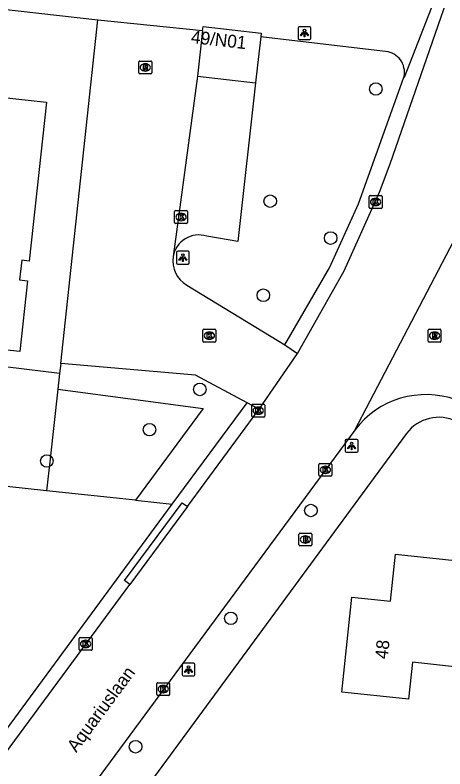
# Model space of a CAD drawing. Extents: x 162398 to 163643, y 386453 to 387397.
# Drawn here: x 162867.5 to 162900.9, y 386898.2 to 386956.9 of the extents above; entities that cross this region are included whole.
import ezdxf

# ---------------------------------------------------------------- set-up
doc = ezdxf.new("R2010")
doc.units = 0
for name, color, linetype in [('IMGEO_Boom', 7, 'Continuous'), ('IMGEO_Brandkraan', 7, 'Continuous'), ('IMGEO_Groenvoorziening', 7, 'Continuous'), ('IMGEO_Kolk', 7, 'Continuous'), ('IMGEO_Lichtpunt', 7, 'Continuous'), ('IMGEO_Openbare_ruimte_label', 7, 'Continuous'), ('IMGEO_Pand', 7, 'Continuous'), ('IMGEO_Pand_nummerreeks', 7, 'Continuous'), ('IMGEO_Parkeervlak_open', 7, 'Continuous'), ('IMGEO_Rijbaan_lokaal_open', 7, 'Continuous'), ('IMGEO_Rioolput', 7, 'Continuous'), ('IMGEO_Voetpad_open', 7, 'Continuous')]:
    doc.layers.add(name, color=color, linetype=linetype)

msp = doc.modelspace()

# ---------------------------------------------------------------- linework, layer by layer
at = {"layer": 'IMGEO_Boom'}
for centre in [(162895.569, 386951.153), (162887.351, 386942.42), (162892.053, 386939.544), (162886.814, 386935.093), (162881.877, 386927.759), (162877.957, 386924.62), (162869.974, 386922.184), (162890.515, 386918.327), (162884.29, 386909.926), (162876.874, 386899.924)]:
    msp.add_circle(centre, 0.489, dxfattribs=at)
at = {"layer": 'IMGEO_Brandkraan'}
for p, q in [((162889.59, 386915.641), (162889.59, 386916.493)), ((162889.665, 386916.567), (162890.517, 386916.567)), ((162890.078, 386916.347), (162890.103, 386916.347)), ((162890.591, 386916.493), (162890.591, 386915.641)), ((162890.101, 386915.787), (162890.076, 386915.787)), ((162890.517, 386915.567), (162889.665, 386915.567))]:
    msp.add_line(p, q, dxfattribs=at)
for points in [[(162889.59, 386915.641), (162889.59, 386916.493)], [(162889.665, 386916.567), (162890.517, 386916.567)], [(162889.938, 386916.267), (162889.938, 386915.867), (162890.151, 386915.867)], [(162890.169, 386916.267), (162889.938, 386916.267)], [(162890.591, 386916.493), (162890.591, 386915.641)], [(162890.117, 386916.186), (162890.063, 386916.186), (162890.063, 386916.11)], [(162890.063, 386916.11), (162890.116, 386916.11)], [(162890.125, 386916.034), (162890.063, 386916.034), (162890.063, 386915.953)], [(162890.063, 386915.953), (162890.125, 386915.953)], [(162890.517, 386915.567), (162889.665, 386915.567)]]:
    msp.add_lwpolyline(points, dxfattribs=at)
for centre, radius, start, end in [((162889.667, 386916.491), 0.0765, 91.55205, 178.44795), ((162889.667, 386916.491), 0.0765, 91.55205, 178.44795), ((162890.173, 386916.122), 0.145, 59.4692, 91.53667), ((162890.515, 386916.491), 0.0765, 1.55205, 88.44795), ((162890.515, 386916.491), 0.0765, 1.55205, 88.44795), ((162890.118, 386916.148), 0.0379, 267.82845, 90.93552), ((162890.126, 386915.993), 0.0404, 269.87594, 90.50774), ((162890.157, 386916.118), 0.251, 268.66757, 293.53466), ((162890.198, 386916.169), 0.0922, 285.51372, 58.15012), ((162890.203, 386915.977), 0.105, 301.31148, 78.98903), ((162889.667, 386915.643), 0.0765, 181.55205, 268.44795), ((162889.667, 386915.643), 0.0765, 181.55205, 268.44795), ((162890.515, 386915.643), 0.0765, 271.55205, 358.44795), ((162890.515, 386915.643), 0.0765, 271.55205, 358.44795)]:
    msp.add_arc(centre, radius, start, end, dxfattribs=at)
for centre, major_axis, ratio, start_param, end_param in [((162890.077, 386916.067), (-0.387, 0.002), 0.722429, 4.712389, 7.853982), ((162890.102, 386916.067), (-0.39, 0.002), 0.717154, 1.570796, 4.712389)]:
    msp.add_ellipse(centre, major_axis=major_axis, ratio=ratio, start_param=start_param, end_param=end_param, dxfattribs=at)
at = {"layer": 'IMGEO_Groenvoorziening'}
for points in [[(162870.971, 386929.009), (162859.945, 386930.347), (162828.236, 386933.706), (162820.477, 386934.559), (162809.62, 386935.738), (162809.662, 386936.561)], [(162871.058, 386929.777), (162870.971, 386929.009)], [(162870.971, 386929.009), (162870.833, 386927.783)], [(162870.833, 386927.783), (162870.223, 386922.353), (162869.944, 386919.868)], [(162870.833, 386927.783), (162882.122, 386926.262), (162876.858, 386919.124)], [(162869.944, 386919.868), (162863.993, 386920.509)], [(162876.858, 386919.124), (162869.944, 386919.868)], [(162876.858, 386919.124), (162879.736, 386918.814)]]:
    msp.add_lwpolyline(points, dxfattribs=at)
at = {"layer": 'IMGEO_Kolk'}
for p, q in [((162895.047, 386941.932), (162895.047, 386942.784)), ((162895.122, 386942.858), (162895.974, 386942.858)), ((162896.048, 386942.784), (162896.048, 386941.932)), ((162895.535, 386942.638), (162895.56, 386942.638)), ((162879.915, 386940.755), (162879.915, 386941.607)), ((162879.99, 386941.681), (162880.842, 386941.681)), ((162880.916, 386941.607), (162880.916, 386940.755)), ((162895.974, 386941.858), (162895.122, 386941.858)), ((162895.558, 386942.078), (162895.533, 386942.078)), ((162880.403, 386941.461), (162880.428, 386941.461)), ((162880.842, 386940.681), (162879.99, 386940.681)), ((162880.426, 386940.901), (162880.401, 386940.901)), ((162882.116, 386931.514), (162882.116, 386932.366)), ((162882.191, 386932.44), (162883.043, 386932.44)), ((162882.604, 386932.22), (162882.629, 386932.22)), ((162883.117, 386932.366), (162883.117, 386931.514)), ((162882.627, 386931.66), (162882.602, 386931.66)), ((162883.043, 386931.44), (162882.191, 386931.44)), ((162885.92, 386925.681), (162885.92, 386926.533)), ((162885.995, 386926.607), (162886.847, 386926.607)), ((162886.408, 386926.387), (162886.433, 386926.387)), ((162886.921, 386926.533), (162886.921, 386925.681)), ((162886.431, 386925.827), (162886.406, 386925.827)), ((162886.847, 386925.607), (162885.995, 386925.607)), ((162891.141, 386921.068), (162891.141, 386921.92)), ((162891.216, 386921.994), (162892.068, 386921.994)), ((162891.629, 386921.774), (162891.654, 386921.774)), ((162892.142, 386921.92), (162892.142, 386921.068)), ((162892.068, 386920.994), (162891.216, 386920.994)), ((162891.652, 386921.214), (162891.627, 386921.214)), ((162872.486, 386907.51), (162872.486, 386908.362)), ((162872.561, 386908.436), (162873.413, 386908.436)), ((162872.974, 386908.216), (162872.999, 386908.216)), ((162873.487, 386908.362), (162873.487, 386907.51)), ((162872.997, 386907.656), (162872.972, 386907.656)), ((162873.413, 386907.436), (162872.561, 386907.436)), ((162878.526, 386903.988), (162878.526, 386904.84)), ((162878.601, 386904.914), (162879.453, 386904.914)), ((162879.014, 386904.694), (162879.039, 386904.694)), ((162879.527, 386904.84), (162879.527, 386903.988)), ((162879.037, 386904.134), (162879.012, 386904.134)), ((162879.453, 386903.914), (162878.601, 386903.914))]:
    msp.add_line(p, q, dxfattribs=at)
for points in [[(162895.047, 386941.932), (162895.047, 386942.784)], [(162895.122, 386942.858), (162895.974, 386942.858)], [(162896.048, 386942.784), (162896.048, 386941.932)], [(162895.368, 386942.558), (162895.491, 386942.558), (162895.491, 386942.407), (162895.621, 386942.558), (162895.785, 386942.558), (162895.639, 386942.407), (162895.792, 386942.158), (162895.64, 386942.158), (162895.555, 386942.322), (162895.491, 386942.255), (162895.491, 386942.158), (162895.368, 386942.158), (162895.368, 386942.558)], [(162879.915, 386940.755), (162879.915, 386941.607)], [(162879.99, 386941.681), (162880.842, 386941.681)], [(162880.916, 386941.607), (162880.916, 386940.755)], [(162895.974, 386941.858), (162895.122, 386941.858)], [(162880.236, 386941.381), (162880.359, 386941.381), (162880.359, 386941.23), (162880.489, 386941.381), (162880.653, 386941.381), (162880.507, 386941.23), (162880.66, 386940.981), (162880.508, 386940.981), (162880.423, 386941.145), (162880.359, 386941.078), (162880.359, 386940.981), (162880.236, 386940.981), (162880.236, 386941.381)], [(162880.842, 386940.681), (162879.99, 386940.681)], [(162882.116, 386931.514), (162882.116, 386932.366)], [(162882.191, 386932.44), (162883.043, 386932.44)], [(162882.437, 386932.14), (162882.56, 386932.14), (162882.56, 386931.989), (162882.69, 386932.14), (162882.854, 386932.14), (162882.708, 386931.989), (162882.861, 386931.74), (162882.709, 386931.74), (162882.624, 386931.904), (162882.56, 386931.837), (162882.56, 386931.74), (162882.437, 386931.74), (162882.437, 386932.14)], [(162883.117, 386932.366), (162883.117, 386931.514)], [(162883.043, 386931.44), (162882.191, 386931.44)], [(162885.92, 386925.681), (162885.92, 386926.533)], [(162885.995, 386926.607), (162886.847, 386926.607)], [(162886.241, 386926.307), (162886.364, 386926.307), (162886.364, 386926.156), (162886.494, 386926.307), (162886.658, 386926.307), (162886.512, 386926.156), (162886.665, 386925.907), (162886.513, 386925.907), (162886.428, 386926.071), (162886.364, 386926.004), (162886.364, 386925.907), (162886.241, 386925.907), (162886.241, 386926.307)], [(162886.921, 386926.533), (162886.921, 386925.681)], [(162886.847, 386925.607), (162885.995, 386925.607)], [(162891.141, 386921.068), (162891.141, 386921.92)], [(162891.216, 386921.994), (162892.068, 386921.994)], [(162891.462, 386921.694), (162891.585, 386921.694), (162891.585, 386921.543), (162891.715, 386921.694), (162891.879, 386921.694), (162891.733, 386921.543), (162891.886, 386921.294), (162891.734, 386921.294), (162891.649, 386921.458), (162891.585, 386921.391), (162891.585, 386921.294), (162891.462, 386921.294), (162891.462, 386921.694)], [(162892.142, 386921.92), (162892.142, 386921.068)], [(162892.068, 386920.994), (162891.216, 386920.994)], [(162872.486, 386907.51), (162872.486, 386908.362)], [(162872.561, 386908.436), (162873.413, 386908.436)], [(162872.807, 386908.136), (162872.93, 386908.136), (162872.93, 386907.985), (162873.06, 386908.136), (162873.224, 386908.136), (162873.078, 386907.985), (162873.231, 386907.736), (162873.079, 386907.736), (162872.994, 386907.9), (162872.93, 386907.833), (162872.93, 386907.736), (162872.807, 386907.736), (162872.807, 386908.136)], [(162873.487, 386908.362), (162873.487, 386907.51)], [(162873.413, 386907.436), (162872.561, 386907.436)], [(162878.526, 386903.988), (162878.526, 386904.84)], [(162878.601, 386904.914), (162879.453, 386904.914)], [(162878.847, 386904.614), (162878.97, 386904.614), (162878.97, 386904.463), (162879.1, 386904.614), (162879.264, 386904.614), (162879.118, 386904.463), (162879.271, 386904.214), (162879.119, 386904.214), (162879.034, 386904.378), (162878.97, 386904.311), (162878.97, 386904.214), (162878.847, 386904.214), (162878.847, 386904.614)], [(162879.527, 386904.84), (162879.527, 386903.988)], [(162879.453, 386903.914), (162878.601, 386903.914)]]:
    msp.add_lwpolyline(points, dxfattribs=at)
for centre, start, end in [((162895.124, 386942.782), 91.55205, 178.44795), ((162895.124, 386942.782), 91.55205, 178.44795), ((162895.972, 386942.782), 1.55205, 88.44795), ((162895.972, 386942.782), 1.55205, 88.44795), ((162879.992, 386941.605), 91.55205, 178.44795), ((162879.992, 386941.605), 91.55205, 178.44795), ((162880.84, 386941.605), 1.55205, 88.44795), ((162880.84, 386941.605), 1.55205, 88.44795), ((162895.124, 386941.934), 181.55205, 268.44795), ((162895.124, 386941.934), 181.55205, 268.44795), ((162895.972, 386941.934), 271.55205, 358.44795), ((162895.972, 386941.934), 271.55205, 358.44795), ((162879.992, 386940.757), 181.55205, 268.44795), ((162879.992, 386940.757), 181.55205, 268.44795), ((162880.84, 386940.757), 271.55205, 358.44795), ((162880.84, 386940.757), 271.55205, 358.44795), ((162882.193, 386932.364), 91.55205, 178.44795), ((162882.193, 386932.364), 91.55205, 178.44795), ((162883.041, 386932.364), 1.55205, 88.44795), ((162883.041, 386932.364), 1.55205, 88.44795), ((162882.193, 386931.516), 181.55205, 268.44795), ((162882.193, 386931.516), 181.55205, 268.44795), ((162883.041, 386931.516), 271.55205, 358.44795), ((162883.041, 386931.516), 271.55205, 358.44795), ((162885.997, 386926.531), 91.55205, 178.44795), ((162885.997, 386926.531), 91.55205, 178.44795), ((162886.845, 386926.531), 1.55205, 88.44795), ((162886.845, 386926.531), 1.55205, 88.44795), ((162885.997, 386925.683), 181.55205, 268.44795), ((162885.997, 386925.683), 181.55205, 268.44795), ((162886.845, 386925.683), 271.55205, 358.44795), ((162886.845, 386925.683), 271.55205, 358.44795), ((162891.218, 386921.918), 91.55205, 178.44795), ((162891.218, 386921.918), 91.55205, 178.44795), ((162892.066, 386921.918), 1.55205, 88.44795), ((162892.066, 386921.918), 1.55205, 88.44795), ((162891.218, 386921.07), 181.55205, 268.44795), ((162891.218, 386921.07), 181.55205, 268.44795), ((162892.066, 386921.07), 271.55205, 358.44795), ((162892.066, 386921.07), 271.55205, 358.44795), ((162872.563, 386908.36), 91.55205, 178.44795), ((162872.563, 386908.36), 91.55205, 178.44795), ((162873.411, 386908.36), 1.55205, 88.44795), ((162873.411, 386908.36), 1.55205, 88.44795), ((162872.563, 386907.512), 181.55205, 268.44795), ((162872.563, 386907.512), 181.55205, 268.44795), ((162873.411, 386907.512), 271.55205, 358.44795), ((162873.411, 386907.512), 271.55205, 358.44795), ((162878.603, 386904.838), 91.55205, 178.44795), ((162878.603, 386904.838), 91.55205, 178.44795), ((162879.451, 386904.838), 1.55205, 88.44795), ((162879.451, 386904.838), 1.55205, 88.44795), ((162878.603, 386903.99), 181.55205, 268.44795), ((162878.603, 386903.99), 181.55205, 268.44795), ((162879.451, 386903.99), 271.55205, 358.44795), ((162879.451, 386903.99), 271.55205, 358.44795)]:
    msp.add_arc(centre, 0.0765, start, end, dxfattribs=at)
for centre, major_axis, ratio, start_param, end_param in [((162895.534, 386942.358), (-0.387, 0.002), 0.722429, 4.712389, 7.853982), ((162895.559, 386942.358), (-0.39, 0.002), 0.717154, 1.570796, 4.712389), ((162880.402, 386941.181), (-0.387, 0.002), 0.722429, 4.712389, 7.853982), ((162880.427, 386941.181), (-0.39, 0.002), 0.717154, 1.570796, 4.712389), ((162882.603, 386931.94), (-0.387, 0.002), 0.722429, 4.712389, 7.853982), ((162882.628, 386931.94), (-0.39, 0.002), 0.717154, 1.570796, 4.712389), ((162886.407, 386926.107), (-0.387, 0.002), 0.722429, 4.712389, 7.853982), ((162886.432, 386926.107), (-0.39, 0.002), 0.717154, 1.570796, 4.712389), ((162891.628, 386921.494), (-0.387, 0.002), 0.722429, 4.712389, 7.853982), ((162891.653, 386921.494), (-0.39, 0.002), 0.717154, 1.570796, 4.712389), ((162872.973, 386907.936), (-0.387, 0.002), 0.722429, 4.712389, 7.853982), ((162872.998, 386907.936), (-0.39, 0.002), 0.717154, 1.570796, 4.712389), ((162879.013, 386904.414), (-0.387, 0.002), 0.722429, 4.712389, 7.853982), ((162879.038, 386904.414), (-0.39, 0.002), 0.717154, 1.570796, 4.712389)]:
    msp.add_ellipse(centre, major_axis=major_axis, ratio=ratio, start_param=start_param, end_param=end_param, dxfattribs=at)
at = {"layer": 'IMGEO_Lichtpunt'}
for p, q in [((162889.519, 386955.916), (162889.519, 386955.109)), ((162889.519, 386955.916), (162889.519, 386955.109)), ((162890.421, 386956.011), (162889.613, 386956.011)), ((162890.421, 386956.011), (162889.613, 386956.011)), ((162890.515, 386955.109), (162890.515, 386955.916)), ((162890.515, 386955.109), (162890.515, 386955.916)), ((162889.613, 386955.015), (162890.421, 386955.015)), ((162889.613, 386955.015), (162890.421, 386955.015)), ((162880.062, 386938.422), (162880.062, 386937.615)), ((162880.062, 386938.422), (162880.062, 386937.615)), ((162880.964, 386938.517), (162880.156, 386938.517)), ((162880.964, 386938.517), (162880.156, 386938.517)), ((162881.058, 386937.615), (162881.058, 386938.422)), ((162881.058, 386937.615), (162881.058, 386938.422)), ((162880.156, 386937.521), (162880.964, 386937.521)), ((162880.156, 386937.521), (162880.964, 386937.521)), ((162893.187, 386923.762), (162893.187, 386922.955)), ((162893.187, 386923.762), (162893.187, 386922.955)), ((162894.089, 386923.857), (162893.281, 386923.857)), ((162894.089, 386923.857), (162893.281, 386923.857)), ((162894.183, 386922.955), (162894.183, 386923.762)), ((162894.183, 386922.955), (162894.183, 386923.762)), ((162893.281, 386922.861), (162894.089, 386922.861)), ((162893.281, 386922.861), (162894.089, 386922.861)), ((162880.497, 386906.338), (162880.497, 386905.531)), ((162880.497, 386906.338), (162880.497, 386905.531)), ((162881.399, 386906.433), (162880.591, 386906.433)), ((162881.399, 386906.433), (162880.591, 386906.433)), ((162881.493, 386905.531), (162881.493, 386906.338)), ((162881.493, 386905.531), (162881.493, 386906.338)), ((162880.591, 386905.437), (162881.399, 386905.437)), ((162880.591, 386905.437), (162881.399, 386905.437))]:
    msp.add_line(p, q, dxfattribs=at)
for points in [[(162889.893, 386955.58), (162889.932, 386955.552), (162889.744, 386955.29), (162889.706, 386955.317), (162889.893, 386955.58)], [(162889.995, 386955.532), (162890.042, 386955.532), (162890.042, 386955.21), (162889.995, 386955.21), (162889.995, 386955.532)], [(162890.105, 386955.552), (162890.143, 386955.579), (162890.33, 386955.317), (162890.291, 386955.289), (162890.105, 386955.552)], [(162880.436, 386938.086), (162880.475, 386938.058), (162880.287, 386937.796), (162880.249, 386937.823), (162880.436, 386938.086)], [(162880.538, 386938.038), (162880.585, 386938.038), (162880.585, 386937.716), (162880.538, 386937.716), (162880.538, 386938.038)], [(162880.648, 386938.058), (162880.686, 386938.085), (162880.873, 386937.823), (162880.834, 386937.795), (162880.648, 386938.058)], [(162893.561, 386923.426), (162893.6, 386923.398), (162893.412, 386923.136), (162893.374, 386923.163), (162893.561, 386923.426)], [(162893.663, 386923.378), (162893.71, 386923.378), (162893.71, 386923.056), (162893.663, 386923.056), (162893.663, 386923.378)], [(162893.773, 386923.398), (162893.811, 386923.425), (162893.998, 386923.163), (162893.959, 386923.135), (162893.773, 386923.398)], [(162880.871, 386906.002), (162880.91, 386905.974), (162880.722, 386905.712), (162880.684, 386905.739), (162880.871, 386906.002)], [(162880.973, 386905.954), (162881.02, 386905.954), (162881.02, 386905.632), (162880.973, 386905.632), (162880.973, 386905.954)], [(162881.083, 386905.974), (162881.121, 386906.001), (162881.308, 386905.739), (162881.269, 386905.711), (162881.083, 386905.974)]]:
    msp.add_lwpolyline(points, dxfattribs=at)
for centre in [(162890.018, 386955.714), (162880.561, 386938.22), (162893.686, 386923.56), (162880.996, 386906.136)]:
    msp.add_circle(centre, 0.0994, dxfattribs=at)
for centre, start, end in [((162889.613, 386955.916), 90, 180), ((162889.613, 386955.916), 90, 180), ((162890.421, 386955.916), 0, 90), ((162890.421, 386955.916), 0, 90), ((162889.613, 386955.109), 180, 270), ((162889.613, 386955.109), 180, 270), ((162890.421, 386955.109), 270, 0), ((162890.421, 386955.109), 270, 360), ((162880.156, 386938.422), 90, 180), ((162880.156, 386938.422), 90, 180), ((162880.964, 386938.422), 0, 90), ((162880.964, 386938.422), 0, 90), ((162880.156, 386937.615), 180, 270), ((162880.156, 386937.615), 180, 270), ((162880.964, 386937.615), 270, 0), ((162880.964, 386937.615), 270, 360), ((162893.281, 386923.762), 90, 180), ((162893.281, 386923.762), 90, 180), ((162894.089, 386923.762), 0, 90), ((162894.089, 386923.762), 0, 90), ((162893.281, 386922.955), 180, 270), ((162893.281, 386922.955), 180, 270), ((162894.089, 386922.955), 270, 0), ((162894.089, 386922.955), 270, 360), ((162880.591, 386906.338), 90, 180), ((162880.591, 386906.338), 90, 180), ((162881.399, 386906.338), 0, 90), ((162881.399, 386906.338), 0, 90), ((162880.591, 386905.531), 180, 270), ((162880.591, 386905.531), 180, 270), ((162881.399, 386905.531), 270, 0), ((162881.399, 386905.531), 270, 360)]:
    msp.add_arc(centre, 0.0946, start, end, dxfattribs=at)
at = {"layer": 'IMGEO_Pand'}
for points in [[(162882.094, 386955.725), (162881.688, 386952.153)], [(162882.094, 386955.725), (162882.127, 386956.013), (162886.646, 386955.499), (162886.615, 386955.228)], [(162886.615, 386955.228), (162886.363, 386953.015), (162886.207, 386951.639)], [(162850.357, 386952.248), (162869.934, 386950.143), (162868.602, 386937.755), (162868.015, 386937.819), (162867.851, 386936.292), (162868.476, 386936.225), (162867.882, 386930.701), (162863.108, 386931.214), (162863.082, 386930.971), (162861.801, 386931.109), (162861.836, 386931.432), (162860.098, 386931.619), (162859.111, 386931.725), (162859.708, 386937.276), (162860.207, 386941.917), (162849.219, 386943.099)], [(162881.688, 386952.153), (162886.207, 386951.639)], [(162904.542, 386906.251), (162904.499, 386905.848), (162898.432, 386906.504), (162898.12, 386903.622), (162897.884, 386903.648), (162892.912, 386904.185), (162893.712, 386911.585), (162896.7, 386911.262), (162897.096, 386914.931), (162901.72, 386914.431), (162901.96, 386916.65), (162905.555, 386916.262)]]:
    msp.add_lwpolyline(points, dxfattribs=at)
at = {"layer": 'IMGEO_Parkeervlak_open'}
msp.add_lwpolyline([(162886.207, 386951.639), (162884.831, 386939.284), (162882.408, 386939.7)], dxfattribs=at)
msp.add_arc((162881.808, 386937.747), 2.043, 72.92513, 170.11837, dxfattribs=at)
at = {"layer": 'IMGEO_Rijbaan_lokaal_open'}
for points in [[(162889.469, 386930.55), (162893.112, 386936.994), (162895.855, 386943.119), (162896.686, 386945.321), (162905.275, 386970.114)], [(162871.058, 386929.777), (162873.936, 386956.547)], [(162873.936, 386956.547), (162882.094, 386955.725)], [(162881.688, 386952.153), (162879.796, 386938.098)], [(162893.927, 386924.59), (162901.627, 386939.333)], [(162880.863, 386935.89), (162888.485, 386931.218)], [(162888.485, 386931.218), (162889.469, 386930.55)], [(162886.5, 386926.213), (162889.469, 386930.55)], [(162885.569, 386926.725), (162881.539, 386928.863), (162871.058, 386929.777)], [(162886.5, 386926.213), (162885.569, 386926.725)], [(162880.904, 386918.631), (162886.42, 386926.104), (162886.5, 386926.213)], [(162893.927, 386924.59), (162875.27, 386899.237), (162869.41, 386891.274), (162864.331, 386884.373), (162862.085, 386881.321), (162857.371, 386874.915), (162855.142, 386871.885), (162843.687, 386856.331), (162841.937, 386853.992)], [(162880.904, 386918.631), (162876.426, 386912.565)], [(162865.209, 386897.338), (162876.426, 386912.565)]]:
    msp.add_lwpolyline(points, dxfattribs=at)
for centre, radius, start, end in [((162881.934, 386937.769), 2.163, 171.25406, 240.32958), ((162899.48, 386920.402), 6.955, 70.28915, 142.9802)]:
    msp.add_arc(centre, radius, start, end, dxfattribs=at)
at = {"layer": 'IMGEO_Rioolput'}
for p, q in [((162877.129, 386952.409), (162877.129, 386953.261)), ((162877.204, 386953.335), (162878.056, 386953.335)), ((162878.13, 386953.261), (162878.13, 386952.409)), ((162877.617, 386953.115), (162877.642, 386953.115)), ((162878.056, 386952.335), (162877.204, 386952.335)), ((162877.64, 386952.555), (162877.615, 386952.555)), ((162899.635, 386931.52), (162899.635, 386932.372)), ((162899.71, 386932.446), (162900.562, 386932.446)), ((162900.123, 386932.226), (162900.148, 386932.226)), ((162900.636, 386932.372), (162900.636, 386931.52)), ((162900.146, 386931.666), (162900.121, 386931.666)), ((162900.562, 386931.446), (162899.71, 386931.446))]:
    msp.add_line(p, q, dxfattribs=at)
for points in [[(162877.129, 386952.409), (162877.129, 386953.261)], [(162877.204, 386953.335), (162878.056, 386953.335)], [(162878.13, 386953.261), (162878.13, 386952.409)], [(162877.718, 386953.033), (162877.466, 386953.035), (162877.466, 386952.635)], [(162877.466, 386952.635), (162877.59, 386952.635), (162877.59, 386952.797), (162877.601, 386952.797)], [(162877.644, 386952.954), (162877.59, 386952.954), (162877.59, 386952.873)], [(162877.59, 386952.873), (162877.642, 386952.873)], [(162877.648, 386952.768), (162877.719, 386952.635), (162877.859, 386952.635), (162877.794, 386952.761)], [(162878.056, 386952.335), (162877.204, 386952.335)], [(162899.635, 386931.52), (162899.635, 386932.372)], [(162899.71, 386932.446), (162900.562, 386932.446)], [(162900.224, 386932.144), (162899.972, 386932.146), (162899.972, 386931.746)], [(162900.636, 386932.372), (162900.636, 386931.52)], [(162899.972, 386931.746), (162900.096, 386931.746), (162900.096, 386931.908), (162900.107, 386931.908)], [(162900.15, 386932.065), (162900.096, 386932.065), (162900.096, 386931.984)], [(162900.096, 386931.984), (162900.148, 386931.984)], [(162900.154, 386931.879), (162900.225, 386931.746), (162900.365, 386931.746), (162900.3, 386931.872)], [(162900.562, 386931.446), (162899.71, 386931.446)]]:
    msp.add_lwpolyline(points, dxfattribs=at)
for centre, radius, start, end in [((162877.206, 386953.259), 0.0765, 91.55205, 178.44795), ((162877.206, 386953.259), 0.0765, 91.55205, 178.44795), ((162878.054, 386953.259), 0.0765, 1.55205, 88.44795), ((162878.054, 386953.259), 0.0765, 1.55205, 88.44795), ((162877.6, 386952.744), 0.0533, 26.02933, 88.69889), ((162877.626, 386953.062), 0.19, 274.7715, 282.96867), ((162877.65, 386952.858), 0.0964, 77.00612, 93.18647), ((162877.664, 386952.915), 0.0378, 276.66336, 79.67722), ((162877.717, 386952.923), 0.109, 350.36119, 89.41601), ((162877.715, 386952.923), 0.112, 277.58423, 350.98172), ((162877.699, 386952.708), 0.108, 29.51342, 73.79051), ((162877.206, 386952.411), 0.0765, 181.55205, 268.44795), ((162877.206, 386952.411), 0.0765, 181.55205, 268.44795), ((162878.054, 386952.411), 0.0765, 271.55205, 358.44795), ((162878.054, 386952.411), 0.0765, 271.55205, 358.44795), ((162899.712, 386932.37), 0.0765, 91.55205, 178.44795), ((162899.712, 386932.37), 0.0765, 91.55205, 178.44795), ((162900.223, 386932.034), 0.109, 350.36119, 89.41601), ((162900.56, 386932.37), 0.0765, 1.55205, 88.44795), ((162900.56, 386932.37), 0.0765, 1.55205, 88.44795), ((162900.106, 386931.855), 0.0533, 26.02933, 88.69889), ((162900.132, 386932.173), 0.19, 274.7715, 282.96867), ((162900.156, 386931.969), 0.0964, 77.00612, 93.18647), ((162900.17, 386932.026), 0.0378, 276.66336, 79.67722), ((162900.221, 386932.034), 0.112, 277.58423, 350.98172), ((162900.205, 386931.819), 0.108, 29.51342, 73.79051), ((162899.712, 386931.522), 0.0765, 181.55205, 268.44795), ((162899.712, 386931.522), 0.0765, 181.55205, 268.44795), ((162900.56, 386931.522), 0.0765, 271.55205, 358.44795), ((162900.56, 386931.522), 0.0765, 271.55205, 358.44795)]:
    msp.add_arc(centre, radius, start, end, dxfattribs=at)
for centre, major_axis, ratio, start_param, end_param in [((162877.616, 386952.835), (-0.387, 0.002), 0.722429, 4.712389, 7.853982), ((162877.641, 386952.835), (-0.39, 0.002), 0.717154, 1.570796, 4.712389), ((162900.122, 386931.946), (-0.387, 0.002), 0.722429, 4.712389, 7.853982), ((162900.147, 386931.946), (-0.39, 0.002), 0.717154, 1.570796, 4.712389)]:
    msp.add_ellipse(centre, major_axis=major_axis, ratio=ratio, start_param=start_param, end_param=end_param, dxfattribs=at)
at = {"layer": 'IMGEO_Voetpad_open'}
for points in [[(162815.68, 386974.834), (162831.565, 386964.807), (162831.24, 386961.405), (162873.936, 386956.547)], [(162900.342, 386958.755), (162900.308, 386958.601), (162897.761, 386952.042), (162897.727, 386951.991)], [(162896.534, 386954.056), (162886.615, 386955.228)], [(162888.485, 386931.218), (162891.957, 386937.22), (162894.215, 386942.213), (162897.727, 386951.991)], [(162879.736, 386918.814), (162885.569, 386926.725)], [(162897.961, 386924.315), (162846.211, 386853.845), (162843.791, 386850.525), (162842.468, 386848.856)], [(162861.792, 386900.876), (162866.149, 386900.387), (162875.032, 386912.434), (162879.736, 386918.814)], [(162876.426, 386912.565), (162876.015, 386912.869), (162880.497, 386918.932), (162880.904, 386918.631)]]:
    msp.add_lwpolyline(points, dxfattribs=at)
for centre, radius, start, end in [((162896.166, 386952.467), 1.631, 343.05283, 76.97928), ((162900.465, 386922.483), 3.103, 63.34966, 143.8075)]:
    msp.add_arc(centre, radius, start, end, dxfattribs=at)

# ---------------------------------------------------------------- texts
at = {"layer": 'IMGEO_Openbare_ruimte_label'}
msp.add_text('Aquariuslaan', height=1, rotation=53.54279, dxfattribs=at).set_placement((162872.263, 386899.422))
at = {"layer": 'IMGEO_Pand_nummerreeks'}
for s, rotation, p in [('49/N01', 353.56568, (162881.153, 386954.74)), ('48', 83.82983, (162896.484, 386906.714))]:
    msp.add_text(s, height=1, rotation=rotation, dxfattribs=at).set_placement(p)

doc.saveas('drawing.dxf')
